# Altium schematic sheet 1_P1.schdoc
size 601 x 429 mm; Symbol: Sheet-Symbol_A4; Device: Sheet-Symbol_A4; @Project Name: Shell Controller; @Page Count: 1; @Update Date: 2024-11-13; @Create Date: 2024-11-05; @Schematic Name: Schematic1; @Page No: 1; @Page Name: P1; Company: EasyEDA.com; Reviewed: EasyEDA; Version: V0.1; Page Size: A4; Part Number: JLCPCB-002; Drawn: EasyEDA; @Board Name: Board1; @Create Time: 20:34:14; @Update Time: 19:59:18; Width: 2338; Height: 1652; Region Start: 1; X Region Count: 6; Y Region Count: 4; Blade Width: 10; Title Block Position: 3
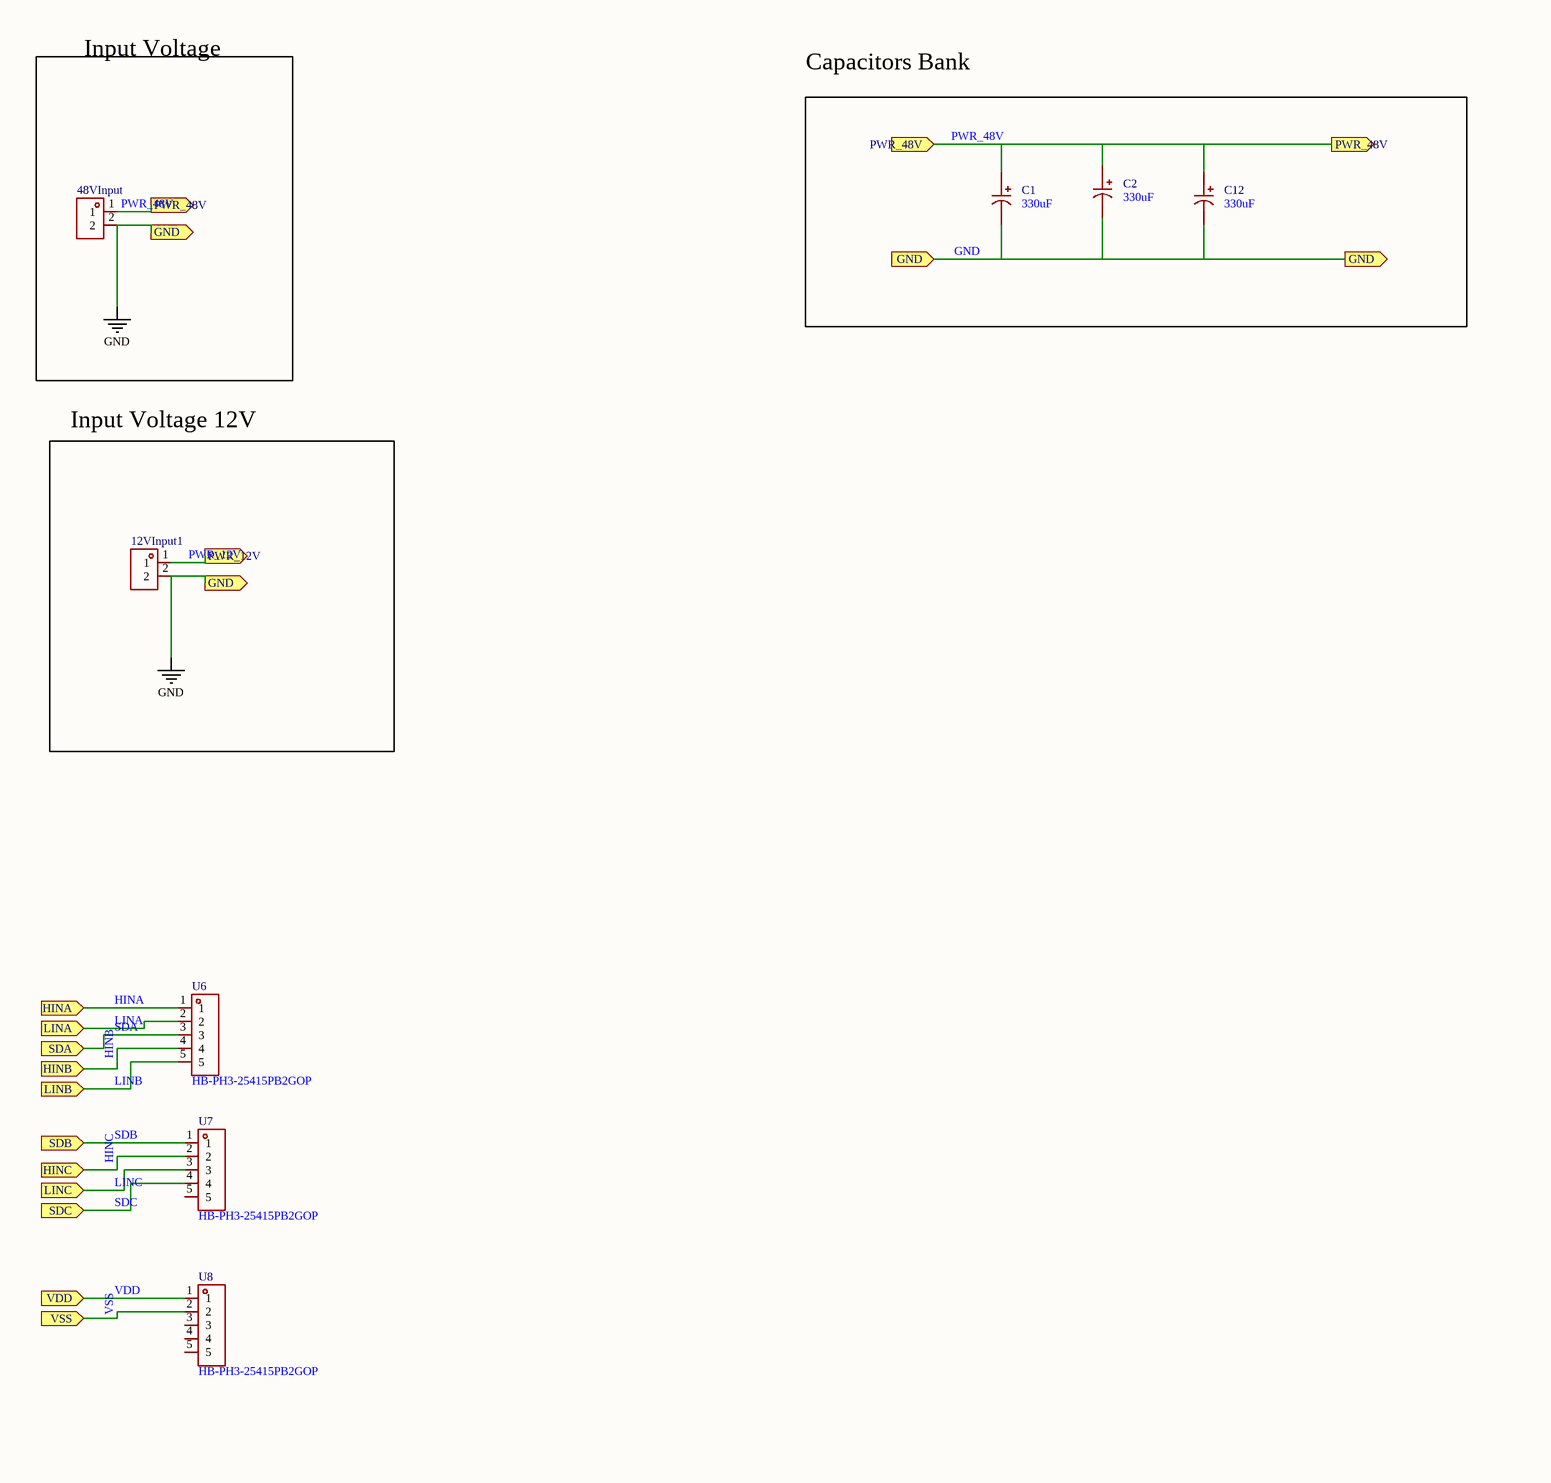
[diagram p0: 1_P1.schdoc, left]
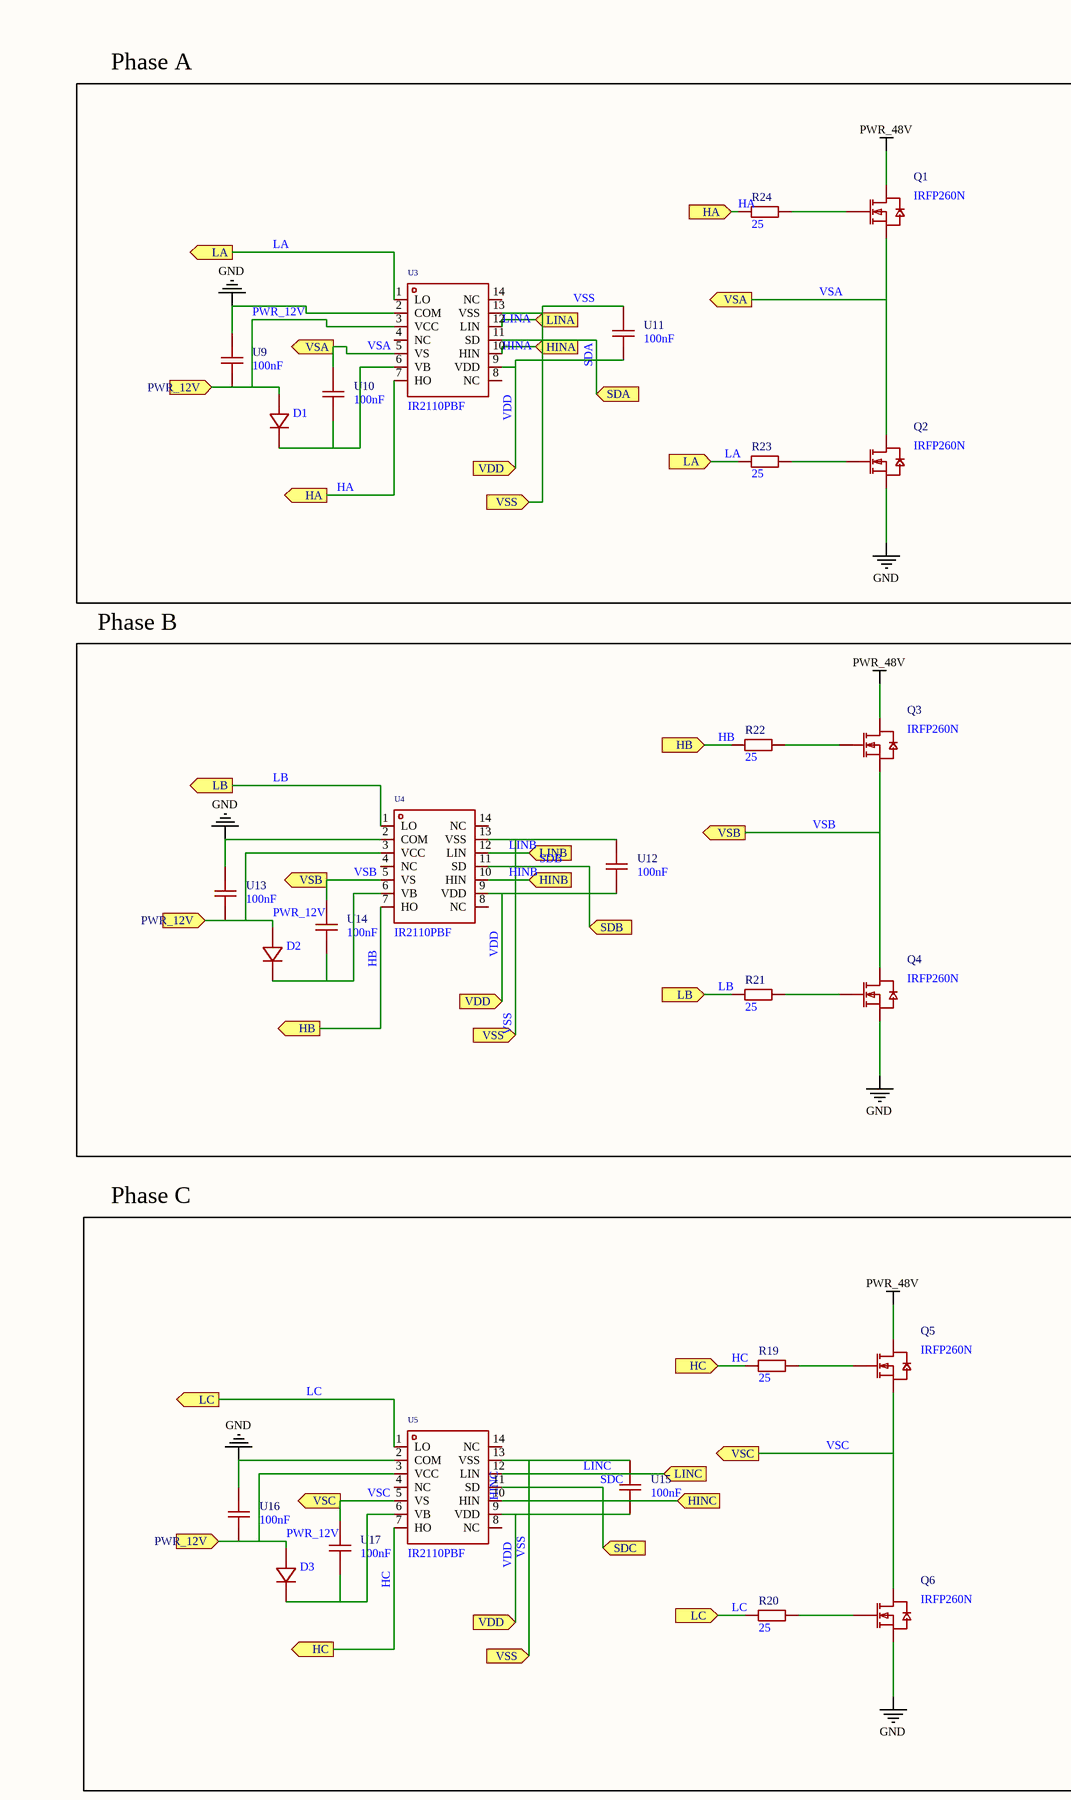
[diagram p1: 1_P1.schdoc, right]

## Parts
12VInput1  DBT50G-9.5-2P-BK-P OGC  [CONN-TH_2P-P9.50_DBT50G-9.5-2P]  (value not drawn)
48VInput  DBT50G-9.5-2P-BK-P OGC  [CONN-TH_2P-P9.50_DBT50G-9.5-2P]  (value not drawn)
C1  330uF  [CAP-TH_BD16.0-P7.50-D0.8-FD]
C2  330uF  [CAP-TH_BD16.0-P7.50-D0.8-FD]
C12  330uF  [CAP-TH_BD16.0-P7.50-D0.8-FD]
D1  (no value)  [DO-41_BD2.4-L4.7-P8.70-D0.9-RD]
D2  (no value)  [DO-41_BD2.4-L4.7-P8.70-D0.9-RD]
D3  (no value)  [DO-41_BD2.4-L4.7-P8.70-D0.9-RD]
Q1  IRFP260N  [TO-247-3_L21.0-W15.9-P5.44-L]
Q2  IRFP260N  [TO-247-3_L21.0-W15.9-P5.44-L]
Q3  IRFP260N  [TO-247-3_L21.0-W15.9-P5.44-L]
Q4  IRFP260N  [TO-247-3_L21.0-W15.9-P5.44-L]
Q5  IRFP260N  [TO-247-3_L21.0-W15.9-P5.44-L]
Q6  IRFP260N  [TO-247-3_L21.0-W15.9-P5.44-L]
R19  25  [RES-TH_BD1.8-L3.2-P7.20-D0.4]
R20  25  [RES-TH_BD1.8-L3.2-P7.20-D0.4]
R21  25  [RES-TH_BD1.8-L3.2-P7.20-D0.4]
R22  25  [RES-TH_BD1.8-L3.2-P7.20-D0.4]
R23  25  [RES-TH_BD1.8-L3.2-P7.20-D0.4]
R24  25  [RES-TH_BD1.8-L3.2-P7.20-D0.4]
U3  IR2110PBF  [DIP-14_L20.0-W7.6-P2.54-LS7.6-BL]
U4  IR2110PBF  [DIP-14_L20.0-W7.6-P2.54-LS7.6-BL]
U5  IR2110PBF  [DIP-14_L20.0-W7.6-P2.54-LS7.6-BL]
U6  HB-PH3-25415PB2GOP  [HDR-TH_5P-P2.54-V-M]
U7  HB-PH3-25415PB2GOP  [HDR-TH_5P-P2.54-V-M]
U8  HB-PH3-25415PB2GOP  [HDR-TH_5P-P2.54-V-M]
U9  100nF  [CAP-TH_L5.5-W4.0-P5.00-D0.5]
U10  100nF  [CAP-TH_L5.5-W4.0-P5.00-D0.5]
U11  100nF  [CAP-TH_L5.5-W4.0-P5.00-D0.5]
U12  100nF  [CAP-TH_L5.5-W4.0-P5.00-D0.5]
U13  100nF  [CAP-TH_L5.5-W4.0-P5.00-D0.5]
U14  100nF  [CAP-TH_L5.5-W4.0-P5.00-D0.5]
U15  100nF  [CAP-TH_L5.5-W4.0-P5.00-D0.5]
U16  100nF  [CAP-TH_L5.5-W4.0-P5.00-D0.5]
U17  100nF  [CAP-TH_L5.5-W4.0-P5.00-D0.5]

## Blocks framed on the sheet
Input Voltage: 48VInput
Phase A: D1 Q1 Q2 R23 R24 U3 U9-U11
Input Voltage 12V: 12VInput1
Phase B: D2 Q3 Q4 R21 R22 U4 U12-U14
Phase C: D3 Q5 Q6 R19 R20 U5 U15-U17

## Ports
GND (in), GND (out), HA (in), HA (out), HB (in), HB (out), HC (in), HC (out), HINA (in), HINB (in), HINC (in), LA (in), LA (out), LB (in), LB (out), LC (in), LC (out), LINA (in), LINB (in), LINC (in), PWR_12V (in), PWR_12V (out), PWR_48V (in), PWR_48V (out), SDA (in), SDB (in), SDC (in), VDD (in), VSA (out), VSB (out), VSC (out), VSS (in)

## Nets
GND: 12VInput1.2 48VInput.2 C1.2 C2.2 C12.2 Q2.3(S) Q4.3(S) Q6.3(S) U3.2(COM) U4.2(COM) U5.2(COM) U9.2 U13.2 U16.2 ; port GND
PWR_48V: 48VInput.1 C1.1 C2.1 C12.1 Q1.2(D) Q3.2(D) Q5.2(D) ; port PWR_48V
HA: R24.1 U3.7(HO) ; port HA
HB: R22.1 U4.7(HO) ; port HB
HC: R19.1 U5.7(HO) ; port HC
HINA: U3.10(HIN) U6.1 ; port HINA
HINB: U4.10(HIN) U6.4 ; port HINB
HINC: U5.10(HIN) U7.2 ; port HINC
LA: R23.1 U3.1(LO) ; port LA
LB: R21.1 U4.1(LO) ; port LB
LC: R20.1 U5.1(LO) ; port LC
LINA: U3.12(LIN) U6.2 ; port LINA
LINB: U4.12(LIN) U6.5 ; port LINB
LINC: U5.12(LIN) U7.3 ; port LINC
PWR_12V: 12VInput1.1 D1.2(A) D2.2(A) D3.2(A) U3.3(VCC) U4.3(VCC) U5.3(VCC) U9.1 U13.1 U16.1 ; port PWR_12V
SDA: U3.11(SD) U6.3 ; port SDA
SDB: U4.11(SD) U7.1 ; port SDB
SDC: U5.11(SD) U7.4 ; port SDC
VDD: U3.9(VDD) U4.9(VDD) U5.9(VDD) U8.1 U11.1 U12.1 U15.1 ; port VDD
VSA: Q1.3(S) Q2.2(D) U3.5(VS) U10.2 ; port VSA
VSB: Q3.3(S) Q4.2(D) U4.5(VS) U14.2 ; port VSB
VSC: Q5.3(S) Q6.2(D) U5.5(VS) U17.2 ; port VSC
VSS: U3.13(VSS) U4.13(VSS) U5.13(VSS) U8.2 U11.2 U12.2 U15.2 ; port VSS
NetD1_1: D1.1(K) U3.6(VB) U10.1
NetD2_1: D2.1(K) U4.6(VB) U14.1
NetD3_1: D3.1(K) U5.6(VB) U17.1
NetQ1_1: Q1.1(G) R24.2
NetQ2_1: Q2.1(G) R23.2
NetQ3_1: Q3.1(G) R22.2
NetQ4_1: Q4.1(G) R21.2
NetQ5_1: Q5.1(G) R19.2
NetQ6_1: Q6.1(G) R20.2

Not connected (* = marked no-connect by the designer): U3 4(NC) 8(NC) 14(NC); U4 4(NC) 8(NC) 14(NC); U5 4(NC) 8(NC) 14(NC); U7 5; U8 3 4 5

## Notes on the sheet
- Capacitors Bank

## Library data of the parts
12VInput1 48VInput = DBT50G-9.5-2P-BK-P OGC: Manufacturer: DORABO(地博电气); Add into BOM: yes; Barrier Type: With Cover Plate; Pitch: 9.5mm; Structure: 1x2P; Pin Location: Corner; Current Rating (Max): 32A; Voltage Rating (Max): 750V; Wire Gauge - AWG: 12~22; Wire Gauge - mm2: 4; Number of PINs Per Row: 2
C1 C2 C12 = SHG330UF100V146EC0462: Manufacturer: KNSCHA(科尼盛); Add into BOM: yes; Tolerance: ±20%; Lifetime @ Temp: 10000hrs@105℃
D1-D3 = 1N4007: Symbol: D_1N4007; Convert to PCB: yes
Q1-Q6 = IRFP260N: Manufacturer: minos(迈诺斯); Add into BOM: yes
R19-R24 = Res_AXIAL-1/8W: Symbol: Res; Convert to PCB: yes
U3-U5 = IR2110PBF: Manufacturer: Infineon(英飞凌); Symbol: IR2110PBF_C2967; Add into BOM: yes; Driven Configuration: Half Bridge; Load Type: MOSFET；IGBT; Number of Drivers: 2; Peak Output Current(sink): 2A; Supply Voltage: 3.3V~20V; Rise Time: 25ns; Fall Time: 17ns
U6-U8 = HB-PH3-25415PB2GOP: Manufacturer: HANBO(汉博); Add into BOM: yes; Pin Structure: 1x5P; Pitch: 2.54mm; Circluar Pins/Square Pins: Square Pins; Current Rating (Max): 3A; Voltage Rating (Max): 250V; Soldering Temperature(Max): 260℃
U9-U17 = Y5P102K1KV16CC0008: Manufacturer: KNSCHA(科尼盛); Add into BOM: yes; Tolerance: ±10%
